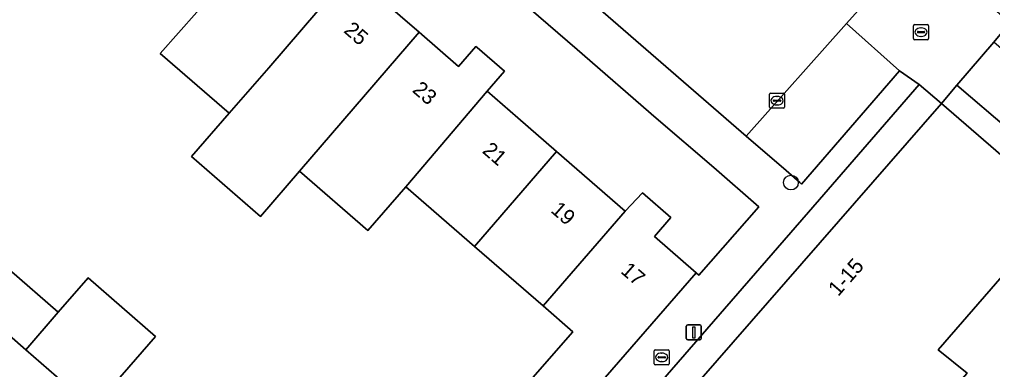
# Model space of a CAD drawing. Extents: x 158472 to 159562, y 388525 to 389606.
# Drawn here: x 158911.2 to 158975.4, y 388782.4 to 388805.5 of the extents above; entities that cross this region are included whole.
import ezdxf

# ---------------------------------------------------------------- set-up
doc = ezdxf.new("R2010")
doc.units = 0
for name, color, linetype in [('IMGEO_Boom', 7, 'Continuous'), ('IMGEO_Brandkraan', 7, 'Continuous'), ('IMGEO_Erf', 7, 'Continuous'), ('IMGEO_Groenvoorziening', 7, 'Continuous'), ('IMGEO_Kolk', 7, 'Continuous'), ('IMGEO_Lichtmast', 7, 'Continuous'), ('IMGEO_Pand', 7, 'Continuous'), ('IMGEO_Pand_nummerreeks', 7, 'Continuous'), ('IMGEO_Pand_overbouw', 7, 'Continuous'), ('IMGEO_Parkeervlak_open', 7, 'Continuous'), ('IMGEO_Rijbaan_lokaal_open', 7, 'Continuous'), ('IMGEO_Rioolput', 7, 'Continuous'), ('IMGEO_Voetpad_open', 7, 'Continuous')]:
    doc.layers.add(name, color=color, linetype=linetype)

msp = doc.modelspace()

# ---------------------------------------------------------------- linework, layer by layer
at = {"layer": 'IMGEO_Boom'}
msp.add_circle((158962.128, 388794.764), 0.489, dxfattribs=at)
at = {"layer": 'IMGEO_Brandkraan'}
for p, q in [((158953.099, 388782.788), (158953.099, 388783.64)), ((158953.174, 388783.714), (158954.026, 388783.714)), ((158953.358, 388783.208), (158953.358, 388783.22)), ((158953.401, 388783.257), (158953.799, 388783.257)), ((158953.587, 388783.494), (158953.612, 388783.494)), ((158953.842, 388783.22), (158953.842, 388783.208)), ((158954.1, 388783.64), (158954.1, 388782.788)), ((158954.026, 388782.714), (158953.174, 388782.714)), ((158953.796, 388783.171), (158953.398, 388783.171)), ((158953.61, 388782.934), (158953.585, 388782.934))]:
    msp.add_line(p, q, dxfattribs=at)
for points in [[(158953.099, 388782.788), (158953.099, 388783.64)], [(158953.174, 388783.714), (158954.026, 388783.714)], [(158954.1, 388783.64), (158954.1, 388782.788)], [(158954.026, 388782.714), (158953.174, 388782.714)]]:
    msp.add_lwpolyline(points, dxfattribs=at)
for centre, radius, start, end in [((158953.176, 388783.638), 0.0765, 91.55205, 178.44795), ((158953.176, 388783.638), 0.0765, 91.55205, 178.44795), ((158953.398, 388783.217), 0.0403, 85.87752, 175.75265), ((158953.395, 388783.207), 0.0366, 178.93798, 274.71019), ((158953.799, 388783.214), 0.043, 264.86636, 352.45326), ((158953.803, 388783.219), 0.0386, 1.73085, 96.63898), ((158954.024, 388783.638), 0.0765, 1.55205, 88.44795), ((158954.024, 388783.638), 0.0765, 1.55205, 88.44795), ((158953.176, 388782.79), 0.0765, 181.55205, 268.44795), ((158953.176, 388782.79), 0.0765, 181.55205, 268.44795), ((158954.024, 388782.79), 0.0765, 271.55205, 358.44795), ((158954.024, 388782.79), 0.0765, 271.55205, 358.44795)]:
    msp.add_arc(centre, radius, start, end, dxfattribs=at)
for centre, major_axis, ratio, start_param, end_param in [((158953.586, 388783.214), (-0.387, 0.002), 0.722429, 4.712389, 7.853982), ((158953.611, 388783.214), (-0.39, 0.002), 0.717154, 1.570796, 4.712389)]:
    msp.add_ellipse(centre, major_axis=major_axis, ratio=ratio, start_param=start_param, end_param=end_param, dxfattribs=at)
at = {"layer": 'IMGEO_Erf'}
for points in [[(158945.099, 388781.884), (158947.724, 388784.903), (158945.765, 388786.607), (158941.241, 388790.541), (158936.716, 388794.476), (158934.203, 388791.586), (158929.695, 388795.506), (158927.128, 388792.519), (158922.564, 388796.487), (158925.042, 388799.336), (158920.505, 388803.282), (158924.117, 388807.418)], [(158935.074, 388806.887), (158937.593, 388804.696), (158940.193, 388802.435), (158941.34, 388803.758), (158941.42, 388803.688), (158943.23, 388802.122), (158942.08, 388800.794), (158944.103, 388799.035), (158946.649, 388796.821), (158949.346, 388794.476), (158951.196, 388792.868), (158952.336, 388794.077), (158954.208, 388792.449), (158953.118, 388791.196), (158955.879, 388788.794), (158956.051, 388788.641), (158960.014, 388793.15), (158957.047, 388795.76), (158953.243, 388799.022), (158948.022, 388803.56), (158944.187, 388806.882)], [(158910.517, 388789.015), (158913.763, 388786.192), (158915.734, 388788.458), (158920.194, 388784.58), (158916.076, 388779.845)]]:
    msp.add_lwpolyline(points, dxfattribs=at)
at = {"layer": 'IMGEO_Groenvoorziening'}
msp.add_lwpolyline([(158976.08, 388788.574), (158971.836, 388783.709), (158973.769, 388782.177), (158970.642, 388778.593), (158974.692, 388775.059), (158973.202, 388773.351), (158967.222, 388778.568), (158964.032, 388774.912), (158970.061, 388769.651), (158968.586, 388767.96), (158962.667, 388773.125), (158958.899, 388776.413), (158960.247, 388777.957), (158956.04, 388781.627), (158972.066, 388799.994), (158970.588, 388801.233), (158964.006, 388793.644), (158952.352, 388780.205), (158936.523, 388761.952), (158947.491, 388752.738), (158937.778, 388742.309)], dxfattribs=at)
at = {"layer": 'IMGEO_Kolk'}
for p, q in [((158960.712, 388799.747), (158960.712, 388800.599)), ((158960.787, 388800.673), (158961.639, 388800.673)), ((158961.713, 388800.599), (158961.713, 388799.747)), ((158960.971, 388800.167), (158960.971, 388800.179)), ((158961.409, 388800.13), (158961.011, 388800.13)), ((158961.014, 388800.216), (158961.412, 388800.216)), ((158961.223, 388799.893), (158961.198, 388799.893)), ((158961.2, 388800.453), (158961.225, 388800.453)), ((158961.455, 388800.179), (158961.455, 388800.167)), ((158961.639, 388799.673), (158960.787, 388799.673))]:
    msp.add_line(p, q, dxfattribs=at)
for points in [[(158960.712, 388799.747), (158960.712, 388800.599)], [(158960.787, 388800.673), (158961.639, 388800.673)], [(158961.713, 388800.599), (158961.713, 388799.747)], [(158961.639, 388799.673), (158960.787, 388799.673)]]:
    msp.add_lwpolyline(points, dxfattribs=at)
for centre, radius, start, end in [((158960.789, 388800.597), 0.0765, 91.55205, 178.44795), ((158960.789, 388800.597), 0.0765, 91.55205, 178.44795), ((158961.637, 388800.597), 0.0765, 1.55205, 88.44795), ((158961.637, 388800.597), 0.0765, 1.55205, 88.44795), ((158961.011, 388800.176), 0.0403, 85.87752, 175.75265), ((158961.008, 388800.166), 0.0366, 178.93798, 274.71019), ((158961.412, 388800.173), 0.043, 264.86636, 352.45326), ((158961.416, 388800.178), 0.0386, 1.73085, 96.63898), ((158960.789, 388799.749), 0.0765, 181.55205, 268.44795), ((158960.789, 388799.749), 0.0765, 181.55205, 268.44795), ((158961.637, 388799.749), 0.0765, 271.55205, 358.44795), ((158961.637, 388799.749), 0.0765, 271.55205, 358.44795)]:
    msp.add_arc(centre, radius, start, end, dxfattribs=at)
for centre, major_axis, ratio, start_param, end_param in [((158961.199, 388800.173), (-0.387, 0.002), 0.722429, 4.712389, 7.853982), ((158961.224, 388800.173), (-0.39, 0.002), 0.717154, 1.570796, 4.712389)]:
    msp.add_ellipse(centre, major_axis=major_axis, ratio=ratio, start_param=start_param, end_param=end_param, dxfattribs=at)
at = {"layer": 'IMGEO_Lichtmast'}
for p, q in [((158955.224, 388784.463), (158955.224, 388785.263)), ((158955.224, 388785.263), (158955.224, 388784.463)), ((158955.324, 388785.363), (158956.114, 388785.363)), ((158956.114, 388785.363), (158955.324, 388785.363)), ((158956.214, 388785.263), (158956.214, 388784.463)), ((158956.214, 388784.463), (158956.214, 388785.263)), ((158956.114, 388784.363), (158955.324, 388784.363)), ((158955.324, 388784.363), (158956.114, 388784.363))]:
    msp.add_line(p, q, dxfattribs=at)
msp.add_lwpolyline([(158955.644, 388785.238), (158955.794, 388785.238), (158955.794, 388784.488), (158955.644, 388784.488), (158955.644, 388785.238)], dxfattribs=at)
for centre, start, end in [((158955.324, 388785.263), 90, 180), ((158955.324, 388785.263), 90, 180), ((158956.114, 388785.263), 0, 90), ((158956.114, 388785.263), 360, 90), ((158955.324, 388784.463), 180, 270), ((158955.324, 388784.463), 180, 270), ((158956.114, 388784.463), 270, 0), ((158956.114, 388784.463), 270, 0)]:
    msp.add_arc(centre, 0.1, start, end, dxfattribs=at)
at = {"layer": 'IMGEO_Pand'}
for points in [[(158933.067, 388808.632), (158931.246, 388810.215), (158929.162, 388812.027), (158928.766, 388812.372), (158928.581, 388812.533), (158924.117, 388807.418), (158920.505, 388803.282), (158925.042, 388799.336), (158927.663, 388802.35)], [(158937.593, 388804.696), (158935.074, 388806.887), (158933.067, 388808.632), (158927.663, 388802.35), (158925.042, 388799.336), (158922.564, 388796.487), (158927.128, 388792.519), (158929.695, 388795.506)], [(158929.695, 388795.506), (158934.203, 388791.586), (158936.716, 388794.476), (158942.08, 388800.794), (158943.23, 388802.122), (158941.42, 388803.688), (158941.34, 388803.758), (158940.193, 388802.435), (158937.593, 388804.696)], [(158946.649, 388796.821), (158944.103, 388799.035), (158942.08, 388800.794), (158936.716, 388794.476), (158941.241, 388790.541)], [(158971.836, 388783.709), (158976.08, 388788.574), (158980.022, 388793.096), (158978.901, 388794.068), (158972.066, 388799.994), (158956.04, 388781.627), (158960.247, 388777.957), (158958.899, 388776.413), (158962.667, 388773.125), (158968.586, 388767.96), (158970.061, 388769.651), (158964.032, 388774.912), (158967.222, 388778.568), (158973.202, 388773.351), (158974.692, 388775.059), (158970.642, 388778.593), (158973.769, 388782.177)], [(158946.649, 388796.821), (158941.241, 388790.541), (158945.765, 388786.607), (158951.196, 388792.868), (158949.346, 388794.476)], [(158955.879, 388788.794), (158953.118, 388791.196), (158954.208, 388792.449), (158952.336, 388794.077), (158951.196, 388792.868), (158945.765, 388786.607), (158947.724, 388784.903), (158945.099, 388781.884), (158947.815, 388779.521)], [(158913.763, 388786.192), (158910.517, 388789.015), (158908.37, 388786.546), (158911.63, 388783.712)], [(158913.763, 388786.192), (158911.63, 388783.712), (158914.673, 388781.065), (158916.076, 388779.845), (158920.194, 388784.58), (158915.734, 388788.458)]]:
    msp.add_lwpolyline(points, close=True, dxfattribs=at)
at = {"layer": 'IMGEO_Pand_overbouw'}
msp.add_lwpolyline([(158976.586, 388805.308), (158975.512, 388804.045), (158973.085, 388801.192), (158972.066, 388799.994), (158978.901, 388794.068), (158979.977, 388795.292), (158982.411, 388798.058), (158983.491, 388799.286)], close=True, dxfattribs=at)
at = {"layer": 'IMGEO_Parkeervlak_open'}
msp.add_lwpolyline([(158969.296, 388802.14), (158965.788, 388805.265), (158959.175, 388797.838), (158961.808, 388795.552), (158962.708, 388794.771), (158962.832, 388794.663)], close=True, dxfattribs=at)
at = {"layer": 'IMGEO_Rijbaan_lokaal_open'}
msp.add_lwpolyline([(158927.054, 388829.223), (158926.892, 388829.365), (158924.182, 388826.315), (158927.08, 388823.739), (158928.05, 388824.862), (158959.175, 388797.838), (158965.788, 388805.265), (158969.246, 388809.149), (158962.92, 388814.631), (158959.478, 388810.733), (158956.854, 388807.76), (158955.341, 388809.01), (158939.082, 388823.238), (158937.005, 388824.955), (158942.646, 388831.471)], dxfattribs=at)
msp.add_lwpolyline([(158979.977, 388795.292), (158982.411, 388798.058), (158975.512, 388804.045), (158973.085, 388801.192)], close=True, dxfattribs=at)
at = {"layer": 'IMGEO_Rioolput'}
for p, q in [((158970.216, 388804.276), (158970.216, 388805.128)), ((158970.291, 388805.202), (158971.143, 388805.202)), ((158971.217, 388805.128), (158971.217, 388804.276)), ((158970.475, 388804.696), (158970.475, 388804.708)), ((158970.913, 388804.659), (158970.515, 388804.659)), ((158970.518, 388804.745), (158970.916, 388804.745)), ((158970.727, 388804.422), (158970.702, 388804.422)), ((158970.704, 388804.982), (158970.729, 388804.982)), ((158970.959, 388804.708), (158970.959, 388804.696)), ((158971.143, 388804.202), (158970.291, 388804.202))]:
    msp.add_line(p, q, dxfattribs=at)
for points in [[(158970.216, 388804.276), (158970.216, 388805.128)], [(158970.291, 388805.202), (158971.143, 388805.202)], [(158971.217, 388805.128), (158971.217, 388804.276)], [(158971.143, 388804.202), (158970.291, 388804.202)]]:
    msp.add_lwpolyline(points, dxfattribs=at)
for centre, radius, start, end in [((158970.293, 388805.126), 0.0765, 91.55205, 178.44795), ((158970.293, 388805.126), 0.0765, 91.55205, 178.44795), ((158971.141, 388805.126), 0.0765, 1.55205, 88.44795), ((158971.141, 388805.126), 0.0765, 1.55205, 88.44795), ((158970.515, 388804.705), 0.0403, 85.87752, 175.75265), ((158970.512, 388804.695), 0.0366, 178.93798, 274.71019), ((158970.916, 388804.702), 0.043, 264.86636, 352.45326), ((158970.92, 388804.707), 0.0386, 1.73085, 96.63898), ((158970.293, 388804.278), 0.0765, 181.55205, 268.44795), ((158970.293, 388804.278), 0.0765, 181.55205, 268.44795), ((158971.141, 388804.278), 0.0765, 271.55205, 358.44795), ((158971.141, 388804.278), 0.0765, 271.55205, 358.44795)]:
    msp.add_arc(centre, radius, start, end, dxfattribs=at)
for centre, major_axis, ratio, start_param, end_param in [((158970.703, 388804.702), (-0.387, 0.002), 0.722429, 4.712389, 7.853982), ((158970.728, 388804.702), (-0.39, 0.002), 0.717154, 1.570796, 4.712389)]:
    msp.add_ellipse(centre, major_axis=major_axis, ratio=ratio, start_param=start_param, end_param=end_param, dxfattribs=at)
at = {"layer": 'IMGEO_Voetpad_open'}
for points in [[(158930.748, 388841.919), (158934.325, 388838.808), (158937.853, 388835.702), (158942.646, 388831.471), (158937.005, 388824.955), (158939.082, 388823.238), (158942.175, 388826.678), (158958.574, 388812.427), (158955.341, 388809.01), (158956.854, 388807.76), (158959.478, 388810.733), (158962.92, 388814.631), (158969.246, 388809.149), (158965.788, 388805.265), (158969.296, 388802.14), (158970.588, 388801.233), (158972.066, 388799.994), (158973.085, 388801.192), (158975.512, 388804.045), (158976.586, 388805.308), (158975.565, 388806.198), (158975.043, 388806.651), (158969.67, 388811.315), (158964.083, 388816.165)], [(158952.352, 388780.205), (158964.006, 388793.644), (158970.588, 388801.233), (158969.296, 388802.14), (158962.832, 388794.663), (158962.708, 388794.771), (158961.808, 388795.552), (158959.175, 388797.838), (158928.05, 388824.862), (158927.08, 388823.739), (158930.914, 388820.395), (158932.924, 388818.579), (158932.03, 388817.43), (158935.123, 388814.752), (158938.98, 388811.457), (158944.187, 388806.882), (158948.022, 388803.56), (158953.243, 388799.022), (158957.047, 388795.76), (158960.014, 388793.15), (158956.051, 388788.641), (158955.879, 388788.794), (158947.815, 388779.521)]]:
    msp.add_lwpolyline(points, dxfattribs=at)
for points in [[(158973.085, 388801.192), (158972.066, 388799.994), (158978.901, 388794.068), (158979.977, 388795.292)], [(158914.673, 388781.065), (158911.63, 388783.712), (158908.37, 388786.546), (158905.64, 388788.924), (158902.489, 388791.686), (158899.316, 388794.468), (158895.45, 388797.816), (158892.838, 388800.078), (158891.577, 388798.482), (158893.955, 388796.45), (158894.069, 388795.98), (158893.757, 388795.245), (158933.895, 388760.26), (158936.523, 388761.952), (158935.096, 388763.304), (158932.785, 388765.308), (158929.651, 388768.031), (158926.498, 388770.77), (158925.201, 388771.897), (158923.693, 388773.175), (158920.494, 388775.964), (158917.379, 388778.68), (158916.076, 388779.845)]]:
    msp.add_lwpolyline(points, close=True, dxfattribs=at)

# ---------------------------------------------------------------- texts
at = {"layer": 'IMGEO_Pand_nummerreeks'}
for s, rotation, p in [('25', 318.98768, (158932.554, 388804.732)), ('23', 318.98937, (158937.079, 388800.797)), ('21', 318.99246, (158941.697, 388796.781)), ('19', 318.99246, (158946.219, 388792.849)), ('1-15', 48.89622, (158965.248, 388787.191)), ('17', 318.97622, (158950.83, 388788.839))]:
    msp.add_text(s, height=1, rotation=rotation, dxfattribs=at).set_placement(p)

doc.saveas('drawing.dxf')
